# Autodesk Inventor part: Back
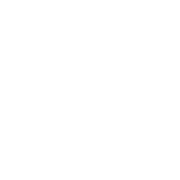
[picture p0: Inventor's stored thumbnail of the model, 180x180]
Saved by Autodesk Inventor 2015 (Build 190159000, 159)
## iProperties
Created: 2016-02
Part Number: Back
Material: Wood (Birch)
Document SubType Name: Modeling
Designer: Hafliði
Density: 0.55 g/cm^3
Appearance: Birch - Natural Polished
Mass: 302.5 g
Surface Area: 1195 cm^2
Volume: 550 cm^3
Author: Hafliði
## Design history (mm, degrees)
sketch "Sketch1"
  geometry: L1 (-100, 137.5)-(100, 137.5); L2 (100, 137.5)-(100, -137.5); L3 (100, -137.5)-(-100, -137.5); L4 (-100, -137.5)-(-100, 137.5); L5 (-100, 137.5)-(100, -137.5); L6 (100, 137.5)-(-100, -137.5); 1 further point
  constraints: 12 end point, 2 midpoint, 2 parallel, 1 horizontal, 1 perpendicular
  dimensions: "d0" = 200 distance of L2.end L3.end; "d1" = 275 distance of L1.end L2.end
extrude "Extrusion1" new body sketch "Sketch1" distance "d2" = 10; taper "d3" = 0 deg
body "Solid1"
